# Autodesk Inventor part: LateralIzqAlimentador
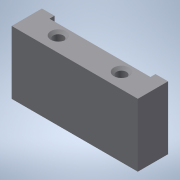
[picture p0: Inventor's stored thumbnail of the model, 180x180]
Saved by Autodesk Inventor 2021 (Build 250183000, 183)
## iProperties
Created: 2021-02
Part Number: LateralIzqAlimentador
Material: Genérico
Document SubType Name: Modeling
Designer: ATOUZA
Density: 1 g/cm^3
Appearance: Valor por defecto
Author: ATOUZA
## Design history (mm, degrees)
node "Plano de trabajo1"
sketch "Boceto1"
  geometry: L1 (-20, 18)-(20, 18) reference; L2 (20, 20)-(20, 18) reference; L3 (-20, 20)-(20, 20) reference; L4 (-20, 18)-(-20, 20) reference; L5 (20, 20)-(-20, 20); L6 (25, 26)-(-25, 26); L7 (-25, 26)-(-25, 18); L8 (-25, 18)-(-20, 18); L9 (-20, 18)-(-20, 20); L10 (25, 26)-(25, 18); L11 (25, 18)-(20, 18); L12 (20, 18)-(20, 20); L13 (25, 26)-(-25, 26); 1 further point
  constraints: 18 end point, 3 horizontal, 3 parallel, 2 point on line, 1 perpendicular
  dimensions: "d1" = 5 distance of L8.end L7.end; "d2" = 5 distance of L10.end L11.end; "d3" = 8 distance of L6.start L10.end; "d4" = 50 distance of L6.start L6.end
extrude "Extrusión2" new body sketch "Boceto1" distance "d17" = 25; taper "d18" = 0 deg
sketch "Boceto4"
  geometry: L1 (-25, 26)-(25, 26) reference; L2 (25, 26)-(-25, 26); L3 (-25, 26)-(-25, 34); L4 (-25, 34)-(25, 34); L5 (25, 34)-(25, 26); L6 (-20, 18)-(-20, 20) reference; L7 (-20, 20)-(20, 20); L8 (20, 20)-(20, -20); L9 (20, -20)-(-20, -20); L10 (-20, -20)-(-20, 20); L11 (0, 0)-(0, 30); L12 (0, 30)-(-25, 30); L13 (0, 30)-(25, 30); C1 r 2 at (-12.5, 30); C2 r 2 at (12.5, 30); 1 further point
  constraints: 22 end point, 4 midpoint, 4 parallel, 2 centre point, 2 horizontal, 2 perpendicular, 1 vertical
  dimensions: "d19" = 8 distance of L2.end L3.end; "d22" = 40 distance of L8.end L9.end; "d23" = 40 distance of L7.end L8.end; "d26" = 30 distance of L11.start L11.end; "d27" = 4 diameter of C1; "d28" = 4 diameter of C2
extrude "Extrusión3" join sketch "Boceto4" distance "d20" = 10; taper "d21" = 0 deg
sketch "Boceto5"
  geometry: L1 (-25, -34)-(25, -34) reference; L2 (0, -34)-(0, -26); L3 (-25, -26)-(25, -26) reference; L4 (0, -30)-(-25, -30); L5 (0, -30)-(25, -30); L6 (25, -18)-(25, -34) reference; 3 further points
  constraints: 6 end point, 5 midpoint, 2 horizontal, 1 point on line
hole "Agujero2" sketch "Boceto5" at (-12.5, -30), (12.5, -30) diameter "d29" = 4; stored, may be unused: countersink angle "d33" = 90 deg, drill point angle "d35" = 118 deg; dims "d30" = 6, "d31" = 6, "d32" = 2, "d34" = 8
node "Sólido2"
node "Referencia1"
